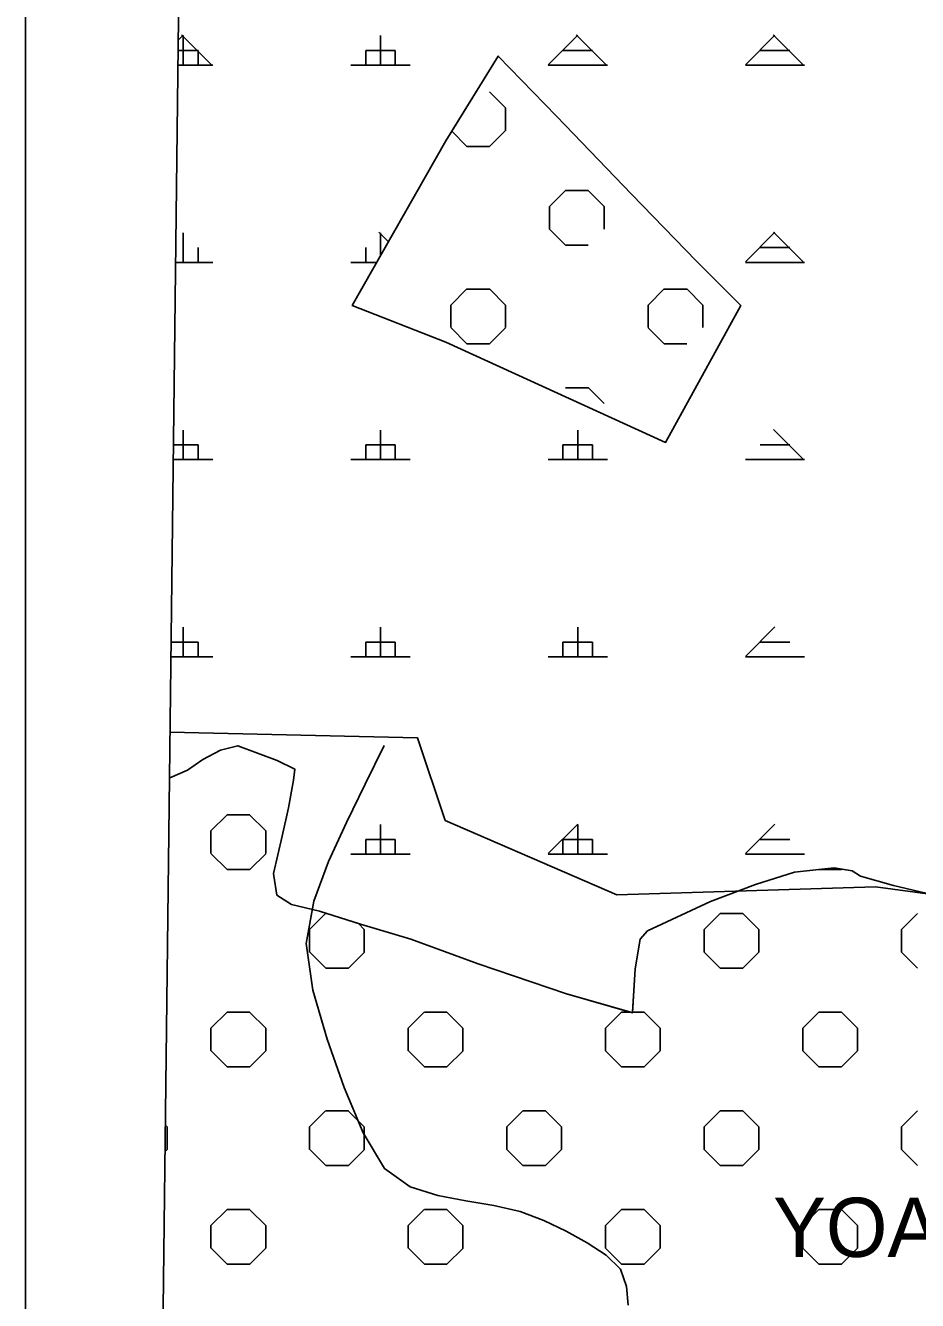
# Model space of a CAD drawing. Extents: x 410727 to 412947, y 4463506 to 4466382.
# Drawn here: x 410732.3 to 410958.4, y 4463784.3 to 4464107.5 of the extents above; entities that cross this region are included whole.
import ezdxf

# ---------------------------------------------------------------- set-up
doc = ezdxf.new("R2010")
doc.units = 0
for name, color, linetype in [('ADAKENARI', 7, 'Continuous'), ('LJ_ÇERÇEVE', 7, 'Continuous'), ('PL_AYA_AGACLANDIRIL', 7, 'Continuous'), ('PL_AYA_ORMAN', 7, 'Continuous'), ('TR_AGACALANI', 7, 'Continuous'), ('TR_AGACLANDIRILACAK', 7, 'Continuous'), ('TR_ORMAN', 7, 'Continuous'), ('YAZI_jeolojik_durum', 7, 'Continuous'), ('Yerlesime_uygunluk_sınırı', 7, 'Continuous')]:
    doc.layers.add(name, color=color, linetype=linetype)

msp = doc.modelspace()

# ---------------------------------------------------------------- linework, layer by layer
at = {"layer": 'ADAKENARI'}
for p, q in [((410781.74, 4463923.78), (410786.13, 4463924.88)), ((410786.13, 4463924.88), (410796.1, 4463921.18)), ((410773.37, 4463918.69), (410777.26, 4463921.38)), ((410777.26, 4463921.38), (410781.74, 4463923.78)), ((410796.1, 4463921.18), (410800.58, 4463918.99)), ((410768.89, 4463916.79), (410773.37, 4463918.69)), ((410800.58, 4463918.99), (410800.28, 4463916.19)), ((410768.78, 4463916.77), (410768.89, 4463916.79)), ((410800.28, 4463916.19), (410798.98, 4463909.2)), ((410798.98, 4463909.2), (410797.34, 4463901.94)), ((410797.34, 4463901.94), (410795.2, 4463892.53)), ((410795.2, 4463892.53), (410795.28, 4463891.94)), ((410795.28, 4463891.94), (410795.99, 4463887.03)), ((410917.38, 4463889.69), (410927.21, 4463892.88)), ((410927.21, 4463892.88), (410937.3, 4463893.95)), ((410937.3, 4463893.95), (410941.82, 4463893.15)), ((410941.82, 4463893.15), (410943.95, 4463891.82)), ((410943.95, 4463891.82), (410952.33, 4463889.5)), ((410905.96, 4463885.43), (410917.38, 4463889.69)), ((410952.33, 4463889.5), (410960.57, 4463887.57)), ((410795.99, 4463887.03), (410799.78, 4463884.64)), ((410890.02, 4463877.98), (410905.96, 4463885.43)), ((410799.78, 4463884.64), (410806.86, 4463882.94)), ((410806.86, 4463882.94), (410817.22, 4463879.64)), ((410817.22, 4463879.64), (410829.97, 4463875.84)), ((410829.97, 4463875.84), (410847.09, 4463869.64)), ((410886.84, 4463868.39), (410888.16, 4463875.85)), ((410888.16, 4463875.85), (410890.02, 4463877.98)), ((410847.09, 4463869.64), (410869.49, 4463862.03)), ((410886.2, 4463857.22), (410886.84, 4463868.39)), ((410869.49, 4463862.03), (410886.2, 4463857.22))]:
    msp.add_line(p, q, dxfattribs=at)
at = {"layer": 'LJ_ÇERÇEVE'}
msp.add_lwpolyline([(410732.32, 4466381.6), (412946.74, 4466381.6), (412946.74, 4463506.16), (410732.32, 4463506.16)], close=True, dxfattribs=at)
at = {"layer": 'PL_AYA_AGACLANDIRIL'}
msp.add_lwpolyline([(410866.93, 4464084.49), (410886, 4464064.59), (410902.35, 4464047.82), (410913.64, 4464036.51), (410894.57, 4464001.79), (410838.9, 4464027.15), (410815.15, 4464036.51), (410838.9, 4464078.24), (410852.14, 4464099.7)], close=True, dxfattribs=at)
for points in [[(410960.57, 4463887.57), (410952.33, 4463889.5), (410943.95, 4463891.82), (410941.82, 4463893.15), (410937.3, 4463893.95), (410927.21, 4463892.88), (410917.38, 4463889.69), (410905.96, 4463885.43), (410890.02, 4463877.98), (410888.16, 4463875.85), (410886.84, 4463868.39), (410886.2, 4463857.22), (410869.49, 4463862.03), (410847.09, 4463869.64), (410829.97, 4463875.84), (410817.22, 4463879.64), (410806.86, 4463882.94), (410799.78, 4463884.64), (410795.99, 4463887.03), (410795.28, 4463891.94), (410795.2, 4463892.53), (410797.34, 4463901.94), (410798.98, 4463909.2), (410800.28, 4463916.19), (410800.58, 4463918.99), (410796.1, 4463921.18), (410786.13, 4463924.88), (410781.74, 4463923.78), (410777.26, 4463921.38), (410773.37, 4463918.69), (410768.89, 4463916.79), (410768.78, 4463916.77)], [(410768.78, 4463916.77), (410766.18, 4463697.48)]]:
    msp.add_lwpolyline(points, dxfattribs=at)
at = {"layer": 'PL_AYA_ORMAN'}
for points in [[(410786.8, 4465435.86), (410768.78, 4463916.77), (410768.89, 4463916.79), (410773.37, 4463918.69), (410777.26, 4463921.38), (410781.74, 4463923.78), (410786.13, 4463924.88), (410796.1, 4463921.18), (410800.58, 4463918.99), (410800.28, 4463916.19), (410798.98, 4463909.2), (410797.34, 4463901.94), (410795.2, 4463892.53), (410795.28, 4463891.94), (410795.99, 4463887.03), (410799.78, 4463884.64), (410806.86, 4463882.94), (410808.72, 4463882.35), (410816.69, 4463879.81), (410817.22, 4463879.64), (410829.97, 4463875.84), (410847.09, 4463869.64), (410869.49, 4463862.03), (410885.75, 4463857.35), (410885.75, 4463857.35), (410885.75, 4463857.35), (410886.2, 4463857.22), (410886.21, 4463857.35), (410886.84, 4463868.39), (410888.16, 4463875.85), (410890.02, 4463877.98), (410905.96, 4463885.43), (410917.38, 4463889.69), (410927.21, 4463892.88), (410933.37, 4463893.53), (410933.37, 4463893.53), (410933.37, 4463893.53), (410937.3, 4463893.95), (410939.27, 4463893.6), (410941.82, 4463893.15), (410943.95, 4463891.82), (410952.33, 4463889.5), (410960.57, 4463887.57)], [(410840.38, 4464080.65), (410852.14, 4464099.7), (410866.93, 4464084.49), (410886, 4464064.59), (410902.35, 4464047.82), (410913.64, 4464036.51), (410894.57, 4464001.79), (410838.9, 4464027.15), (410815.15, 4464036.51), (410838.9, 4464078.24), (410840.38, 4464080.65)]]:
    msp.add_lwpolyline(points, dxfattribs=at)
at = {"layer": 'TR_AGACALANI'}
for p, q in [((410854.01, 4464086.61), (410849.96, 4464090.67)), ((410854.01, 4464080.87), (410854.01, 4464086.61)), ((410844.23, 4464076.79), (410840.38, 4464080.65)), ((410849.97, 4464076.79), (410854.03, 4464080.85)), ((410844.23, 4464076.79), (410849.97, 4464076.79)), ((410865.15, 4464061.61), (410869.21, 4464065.67)), ((410869.23, 4464065.65), (410874.97, 4464065.65)), ((410879.01, 4464061.61), (410874.95, 4464065.67)), ((410865.15, 4464055.87), (410865.15, 4464061.61)), ((410879.01, 4464055.87), (410879.01, 4464061.61)), ((410869.23, 4464051.79), (410865.17, 4464055.85)), ((410869.23, 4464051.79), (410874.97, 4464051.79)), ((410840.15, 4464036.61), (410844.21, 4464040.67)), ((410844.23, 4464040.65), (410849.97, 4464040.65)), ((410854.01, 4464036.61), (410849.96, 4464040.67)), ((410890.15, 4464036.61), (410894.21, 4464040.67)), ((410894.23, 4464040.65), (410899.97, 4464040.65)), ((410904.01, 4464036.61), (410899.95, 4464040.67)), ((410840.15, 4464030.87), (410840.15, 4464036.61)), ((410854.01, 4464030.87), (410854.01, 4464036.61)), ((410890.15, 4464030.87), (410890.15, 4464036.61)), ((410904.01, 4464030.87), (410904.01, 4464036.61)), ((410844.23, 4464026.79), (410840.18, 4464030.85)), ((410849.97, 4464026.79), (410854.03, 4464030.85)), ((410894.23, 4464026.79), (410890.17, 4464030.85)), ((410844.23, 4464026.79), (410849.97, 4464026.79)), ((410894.23, 4464026.79), (410899.97, 4464026.79)), ((410869.23, 4464015.65), (410874.97, 4464015.65)), ((410879.01, 4464011.61), (410874.95, 4464015.67))]:
    msp.add_line(p, q, dxfattribs=at)
at = {"layer": 'TR_AGACLANDIRILACAK'}
for p, q in [((410779.34, 4463903.31), (410783.4, 4463907.36)), ((410783.42, 4463907.35), (410789.16, 4463907.35)), ((410793.2, 4463903.3), (410789.14, 4463907.36)), ((410779.34, 4463897.57), (410779.34, 4463903.31)), ((410793.2, 4463897.57), (410793.2, 4463903.31)), ((410783.42, 4463893.49), (410779.36, 4463897.54)), ((410789.16, 4463893.49), (410793.22, 4463897.54)), ((410783.42, 4463893.49), (410789.16, 4463893.49)), ((410933.42, 4463893.49), (410933.37, 4463893.53)), ((410933.42, 4463893.49), (410939.16, 4463893.49)), ((410939.16, 4463893.49), (410939.27, 4463893.6)), ((410804.34, 4463878.31), (410808.4, 4463882.37)), ((410808.42, 4463882.35), (410808.72, 4463882.35)), ((410904.34, 4463878.31), (410908.4, 4463882.37)), ((410908.42, 4463882.35), (410914.16, 4463882.35)), ((410918.2, 4463878.3), (410914.14, 4463882.36)), ((410954.34, 4463878.31), (410958.4, 4463882.37)), ((410818.2, 4463878.3), (410816.69, 4463879.81)), ((410804.34, 4463872.57), (410804.34, 4463878.31)), ((410818.2, 4463872.57), (410818.2, 4463878.31)), ((410904.34, 4463872.57), (410904.34, 4463878.31)), ((410918.2, 4463872.57), (410918.2, 4463878.31)), ((410954.34, 4463872.57), (410954.34, 4463878.31)), ((410808.42, 4463868.49), (410804.36, 4463872.54)), ((410814.16, 4463868.49), (410818.22, 4463872.54)), ((410908.42, 4463868.49), (410904.36, 4463872.54)), ((410914.16, 4463868.49), (410918.22, 4463872.54)), ((410958.42, 4463868.49), (410954.36, 4463872.54)), ((410808.42, 4463868.49), (410814.16, 4463868.49)), ((410908.42, 4463868.49), (410914.16, 4463868.49)), ((410779.34, 4463853.31), (410783.4, 4463857.37)), ((410783.42, 4463857.35), (410789.16, 4463857.35)), ((410793.2, 4463853.3), (410789.14, 4463857.36)), ((410829.34, 4463853.31), (410833.4, 4463857.37)), ((410833.42, 4463857.35), (410839.16, 4463857.35)), ((410843.2, 4463853.3), (410839.14, 4463857.36)), ((410879.34, 4463853.31), (410883.4, 4463857.37)), ((410883.42, 4463857.35), (410885.75, 4463857.35)), ((410886.21, 4463857.35), (410889.16, 4463857.35)), ((410893.2, 4463853.3), (410889.14, 4463857.36)), ((410929.34, 4463853.31), (410933.4, 4463857.37)), ((410933.42, 4463857.35), (410939.16, 4463857.35)), ((410943.2, 4463853.3), (410939.14, 4463857.36)), ((410779.34, 4463847.57), (410779.34, 4463853.31)), ((410793.2, 4463847.57), (410793.2, 4463853.31)), ((410829.34, 4463847.57), (410829.34, 4463853.31)), ((410843.2, 4463847.57), (410843.2, 4463853.31)), ((410879.34, 4463847.57), (410879.34, 4463853.31)), ((410893.2, 4463847.57), (410893.2, 4463853.31)), ((410929.34, 4463847.57), (410929.34, 4463853.31)), ((410943.2, 4463847.57), (410943.2, 4463853.31)), ((410783.42, 4463843.49), (410779.36, 4463847.54)), ((410789.16, 4463843.49), (410793.22, 4463847.54)), ((410833.42, 4463843.49), (410829.36, 4463847.54)), ((410839.16, 4463843.49), (410843.22, 4463847.54)), ((410883.42, 4463843.49), (410879.36, 4463847.54)), ((410889.16, 4463843.49), (410893.22, 4463847.54)), ((410933.42, 4463843.49), (410929.36, 4463847.54)), ((410939.16, 4463843.49), (410943.22, 4463847.54)), ((410783.42, 4463843.49), (410789.16, 4463843.49)), ((410833.42, 4463843.49), (410839.16, 4463843.49)), ((410883.42, 4463843.49), (410889.16, 4463843.49)), ((410933.42, 4463843.49), (410939.16, 4463843.49)), ((410804.34, 4463828.31), (410808.4, 4463832.37)), ((410808.42, 4463832.35), (410814.16, 4463832.35)), ((410818.2, 4463828.3), (410814.14, 4463832.36)), ((410854.34, 4463828.31), (410858.4, 4463832.37)), ((410858.42, 4463832.35), (410864.16, 4463832.35)), ((410868.2, 4463828.3), (410864.14, 4463832.36)), ((410904.34, 4463828.31), (410908.4, 4463832.37)), ((410908.42, 4463832.35), (410914.16, 4463832.35)), ((410918.2, 4463828.3), (410914.14, 4463832.36)), ((410954.34, 4463828.31), (410958.4, 4463832.37)), ((410768.2, 4463828.3), (410767.74, 4463828.77)), ((410768.2, 4463822.57), (410768.2, 4463828.31)), ((410804.34, 4463822.57), (410804.34, 4463828.31)), ((410818.2, 4463822.57), (410818.2, 4463828.31)), ((410854.34, 4463822.57), (410854.34, 4463828.31)), ((410868.2, 4463822.57), (410868.2, 4463828.31)), ((410904.34, 4463822.57), (410904.34, 4463828.31)), ((410918.2, 4463822.57), (410918.2, 4463828.31)), ((410954.34, 4463822.57), (410954.34, 4463828.31)), ((410767.66, 4463821.98), (410768.22, 4463822.54)), ((410808.42, 4463818.49), (410804.36, 4463822.54)), ((410814.16, 4463818.49), (410818.22, 4463822.54)), ((410858.42, 4463818.49), (410854.36, 4463822.54)), ((410864.16, 4463818.49), (410868.22, 4463822.54)), ((410908.42, 4463818.49), (410904.36, 4463822.54)), ((410914.16, 4463818.49), (410918.22, 4463822.54)), ((410958.42, 4463818.49), (410954.36, 4463822.54)), ((410808.42, 4463818.49), (410814.16, 4463818.49)), ((410858.42, 4463818.49), (410864.16, 4463818.49)), ((410908.42, 4463818.49), (410914.16, 4463818.49)), ((410779.34, 4463803.31), (410783.4, 4463807.37)), ((410783.42, 4463807.35), (410789.16, 4463807.35)), ((410793.2, 4463803.3), (410789.14, 4463807.36)), ((410829.34, 4463803.31), (410833.4, 4463807.37)), ((410833.42, 4463807.35), (410839.16, 4463807.35)), ((410843.2, 4463803.3), (410839.14, 4463807.36)), ((410879.34, 4463803.31), (410883.4, 4463807.37)), ((410883.42, 4463807.35), (410889.16, 4463807.35)), ((410893.2, 4463803.3), (410889.14, 4463807.36)), ((410929.34, 4463803.31), (410933.4, 4463807.37)), ((410933.42, 4463807.35), (410939.16, 4463807.35)), ((410943.2, 4463803.3), (410939.14, 4463807.36)), ((410779.34, 4463797.57), (410779.34, 4463803.31)), ((410793.2, 4463797.57), (410793.2, 4463803.31)), ((410829.34, 4463797.57), (410829.34, 4463803.31)), ((410843.2, 4463797.57), (410843.2, 4463803.31)), ((410879.34, 4463797.57), (410879.34, 4463803.31)), ((410893.2, 4463797.57), (410893.2, 4463803.31)), ((410929.34, 4463797.57), (410929.34, 4463803.31)), ((410943.2, 4463797.57), (410943.2, 4463803.31)), ((410783.42, 4463793.49), (410779.36, 4463797.54)), ((410789.16, 4463793.49), (410793.22, 4463797.54)), ((410833.42, 4463793.49), (410829.36, 4463797.54)), ((410839.16, 4463793.49), (410843.22, 4463797.54)), ((410883.42, 4463793.49), (410879.36, 4463797.54)), ((410889.16, 4463793.49), (410893.22, 4463797.54)), ((410933.42, 4463793.49), (410929.36, 4463797.54)), ((410939.16, 4463793.49), (410943.22, 4463797.54)), ((410783.42, 4463793.49), (410789.16, 4463793.49)), ((410833.42, 4463793.49), (410839.16, 4463793.49)), ((410883.42, 4463793.49), (410889.16, 4463793.49)), ((410933.42, 4463793.49), (410939.16, 4463793.49))]:
    msp.add_line(p, q, dxfattribs=at)
at = {"layer": 'TR_ORMAN'}
for p, q in [((410771, 4464103.7), (410772.3, 4464105)), ((410779.39, 4464097.6), (410771.89, 4464105.1)), ((410772.31, 4464097.41), (410772.31, 4464104.91)), ((410822.31, 4464097.41), (410822.31, 4464104.91)), ((410864.8, 4464097.52), (410872.3, 4464105.02)), ((410879.38, 4464097.6), (410871.88, 4464105.1)), ((410914.8, 4464097.52), (410922.3, 4464105.02)), ((410929.37, 4464097.6), (410921.87, 4464105.1)), ((410770.97, 4464101.16), (410776.06, 4464101.16)), ((410776.06, 4464097.41), (410776.06, 4464101.16)), ((410818.56, 4464097.41), (410818.56, 4464101.16)), ((410818.56, 4464101.16), (410826.06, 4464101.16)), ((410826.06, 4464097.41), (410826.06, 4464101.16)), ((410868.56, 4464101.16), (410876.06, 4464101.16)), ((410918.56, 4464101.16), (410926.06, 4464101.16)), ((410770.92, 4464097.41), (410779.81, 4464097.41)), ((410814.81, 4464097.41), (410829.81, 4464097.41)), ((410864.81, 4464097.41), (410879.81, 4464097.41)), ((410914.81, 4464097.41), (410929.81, 4464097.41)), ((410772.31, 4464047.41), (410772.31, 4464054.91)), ((410824.34, 4464052.65), (410821.92, 4464055.08)), ((410822.31, 4464049.09), (410822.31, 4464054.91)), ((410914.8, 4464047.53), (410922.3, 4464055.03)), ((410929.4, 4464047.58), (410921.9, 4464055.08)), ((410776.06, 4464047.41), (410776.06, 4464051.16)), ((410818.56, 4464047.41), (410818.56, 4464051.16)), ((410918.56, 4464051.16), (410926.06, 4464051.16)), ((410918.56, 4464051.16), (410926.06, 4464051.16)), ((410770.33, 4464047.41), (410779.81, 4464047.41)), ((410814.81, 4464047.41), (410821.36, 4464047.41)), ((410914.81, 4464047.41), (410929.81, 4464047.41)), ((410772.31, 4463997.41), (410772.31, 4464004.91)), ((410822.31, 4463997.41), (410822.31, 4464004.91)), ((410872.31, 4463997.41), (410872.31, 4464004.91)), ((410929.43, 4463997.55), (410921.94, 4464005.05)), ((410769.78, 4464001.16), (410776.06, 4464001.16)), ((410776.06, 4463997.41), (410776.06, 4464001.16)), ((410818.56, 4463997.41), (410818.56, 4464001.16)), ((410818.56, 4464001.16), (410826.06, 4464001.16)), ((410826.06, 4463997.41), (410826.06, 4464001.16)), ((410868.56, 4463997.41), (410868.56, 4464001.16)), ((410868.56, 4464001.16), (410876.06, 4464001.16)), ((410876.06, 4463997.41), (410876.06, 4464001.16)), ((410918.56, 4464001.16), (410926.06, 4464001.16)), ((410769.74, 4463997.41), (410779.81, 4463997.41)), ((410814.81, 4463997.41), (410829.81, 4463997.41)), ((410864.81, 4463997.41), (410879.81, 4463997.41)), ((410914.81, 4463997.41), (410929.81, 4463997.41)), ((410772.31, 4463947.41), (410772.31, 4463954.91)), ((410822.31, 4463947.41), (410822.31, 4463954.91)), ((410872.31, 4463947.41), (410872.31, 4463954.91)), ((410914.8, 4463947.55), (410922.3, 4463955.05)), ((410769.19, 4463951.16), (410776.06, 4463951.16)), ((410776.06, 4463947.41), (410776.06, 4463951.16)), ((410818.56, 4463947.41), (410818.56, 4463951.16)), ((410818.56, 4463951.16), (410826.06, 4463951.16)), ((410826.06, 4463947.41), (410826.06, 4463951.16)), ((410868.56, 4463947.41), (410868.56, 4463951.16)), ((410868.56, 4463951.16), (410876.06, 4463951.16)), ((410876.06, 4463947.41), (410876.06, 4463951.16)), ((410918.56, 4463951.16), (410926.06, 4463951.16)), ((410769.14, 4463947.41), (410779.81, 4463947.41)), ((410814.81, 4463947.41), (410829.81, 4463947.41)), ((410864.81, 4463947.41), (410879.81, 4463947.41)), ((410914.81, 4463947.41), (410929.81, 4463947.41)), ((410822.31, 4463897.41), (410822.31, 4463904.91)), ((410864.8, 4463897.55), (410872.3, 4463905.05)), ((410872.31, 4463897.41), (410872.31, 4463904.91)), ((410914.8, 4463897.55), (410922.3, 4463905.05)), ((410818.56, 4463897.41), (410818.56, 4463901.16)), ((410818.56, 4463901.16), (410826.06, 4463901.16)), ((410818.56, 4463901.16), (410826.06, 4463901.16)), ((410826.06, 4463897.41), (410826.06, 4463901.16)), ((410868.56, 4463897.41), (410868.56, 4463901.16)), ((410868.56, 4463901.16), (410876.06, 4463901.16)), ((410868.56, 4463901.16), (410876.06, 4463901.16)), ((410876.06, 4463897.41), (410876.06, 4463901.16)), ((410918.56, 4463901.16), (410926.06, 4463901.16)), ((410918.56, 4463901.16), (410926.06, 4463901.16)), ((410814.81, 4463897.41), (410829.81, 4463897.41)), ((410814.81, 4463897.41), (410829.81, 4463897.41)), ((410864.81, 4463897.41), (410879.81, 4463897.41)), ((410864.81, 4463897.41), (410879.81, 4463897.41)), ((410914.81, 4463897.41), (410929.81, 4463897.41)), ((410914.81, 4463897.41), (410929.81, 4463897.41))]:
    msp.add_line(p, q, dxfattribs=at)
at = {"layer": 'Yerlesime_uygunluk_sınırı'}
for points in [[(410884.89, 4463553.7), (410894.05, 4463617.91), (410934.73, 4463702.48), (410988.03, 4463765.12), (411028.04, 4463829.11), (411029.72, 4463859.7), (410999.92, 4463882.1), (410947.76, 4463889.1), (410882.25, 4463887.07), (410838.73, 4463905.99), (410831.65, 4463926.92), (410768.92, 4463928.35)], [(410885.11, 4463783.13), (410884.69, 4463787.86), (410883.17, 4463792.19), (410879.5, 4463795.76), (410874.66, 4463798.9), (410869.34, 4463801.83), (410863.73, 4463804.55), (410857.7, 4463806.81), (410850.99, 4463808.35), (410843.94, 4463809.56), (410836.81, 4463810.92), (410829.83, 4463813.12), (410823.36, 4463817.73), (410817.94, 4463826.8), (410813.12, 4463838.27), (410808.75, 4463850.55), (410805.16, 4463862.92), (410803.5, 4463874.77), (410805.38, 4463885.48), (410809.16, 4463895.56), (410813.66, 4463905.42), (410818.4, 4463915.19), (410823.23, 4463924.93)]]:
    msp.add_lwpolyline(points, dxfattribs=at)

# ---------------------------------------------------------------- texts
at = {"layer": 'YAZI_jeolojik_durum'}
msp.add_text('YOA1', height=15, dxfattribs=at).set_placement((410921.82, 4463795.33))

doc.saveas('drawing.dxf')
